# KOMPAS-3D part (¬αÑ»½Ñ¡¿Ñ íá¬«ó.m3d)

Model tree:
1. Эскиз:1
2. Операция выдавливания:1
     Расстояние 1 = 1; Расстояние 2 = 102
3. Эскиз:2
4. Вырезать элемент выдавливания:1
     Расстояние 1 = 10
5. Эскиз:3
6. Операция выдавливания:2
     Расстояние 1 = 0.5; Расстояние 2 = 0.5
7. Эскиз:5
8. Операция выдавливания:3
     Расстояние 1 = 1; Расстояние 2 = 1

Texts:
  Сплав АЛ8  ГОСТ 1583-93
